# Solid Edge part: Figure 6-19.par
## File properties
Accuracy: 0.99
Author: CADCIM
Template: normal.par
Last saved by: CADCIM
Revision: 8
Application: Solid Edge
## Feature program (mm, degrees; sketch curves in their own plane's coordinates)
sketch for "unnamed Protrusion 1" plane through (0, 0, 0) normal (0, 0, 1) x-axis (1, 0, 0)
  line (-55, -37.5) -> (55, -37.5)
  line (55, -37.5) -> (55, 37.5)
  line (55, 37.5) -> (-55, 37.5)
  line (-55, 37.5) -> (-55, -37.5)
extrude "unnamed Protrusion 1" add finite 19.05 along +normal
sketch for "ExtrudedProtrusion_2" plane through (0, 0, 19.05) normal (0, 0, 1) x-axis (0, 1, 0)
  circle centre (-3.8876, -1.0799) radius 22.7058
extrude "ExtrudedProtrusion_2" add finite 41.275 along +normal
sketch for "ExtrudedProtrusion_3" plane through (-55, 0, 9.525) normal (-1, 0, 0) x-axis (0, -1, 0)
  line (29.4545, -9.525) -> (-29.4545, -9.525)
  line (-29.4545, -9.525) -> (-29.4545, 36.1246)
  line (-29.4545, 36.1246) -> (37.5, 36.1246)
  line (37.5, 36.1246) -> (37.5, -9.525)
extrude "ExtrudedProtrusion_3" add finite 15.875 along +normal
sketch for "ExtrudedProtrusion_4" plane through (-7.9375, 29.4545, 22.8248) normal (0, 1, 0) x-axis (0, 0, -1)
  line (22.8248, 62.9375) -> (22.8248, -62.9375)
  line (-35.4203, -62.9375) -> (22.8248, -62.9375)
  line (-35.4203, 62.9375) -> (-35.4203, -62.9375)
  line (-35.4203, 62.9375) -> (22.8248, 62.9375)
extrude "ExtrudedProtrusion_4" add finite 9.525 along +normal
fillet "Round_6" radius 4
fillet "Round_8" radius 6
fillet "Round_10" radius 6
fillet "Round_13" radius 4
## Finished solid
Body 1: solid body, 18 faces, 38 edges, 22 vertices.
  Faces by surface: plane 11, cylinder 5, sphere 1, torus 1
  Edges by curve: line 28, circle 9, ellipse 1
Bounding box of the edges (mm; curved faces can reach further): 125.875 x 76.480 x 60.325, from (-70.875, -37.5, 0) to (55, 38.9795, 60.325).
Cylindrical faces by radius (mm): R4 x4, R22.7058 x1
Toroidal faces (ring radius, tube radius in mm): R26.7058 r4 x1
Spherical faces by radius (mm): R4 x1
Planar faces by outward normal: +x 2, +y 1, +z 4, -x 1, -y 2, -z 1
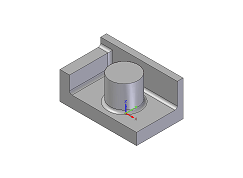
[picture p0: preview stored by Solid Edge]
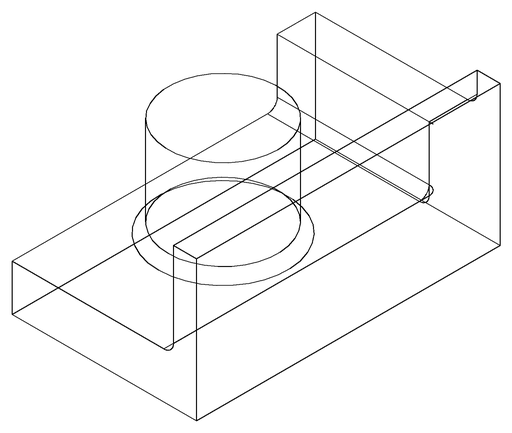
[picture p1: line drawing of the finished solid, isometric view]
